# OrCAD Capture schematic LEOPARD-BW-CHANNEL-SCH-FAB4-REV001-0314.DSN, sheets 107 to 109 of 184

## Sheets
107 064_DDR4 DIMM CPU1 CHG-1: size A3; title: DDR4 DIMM CPU1 CHG-1
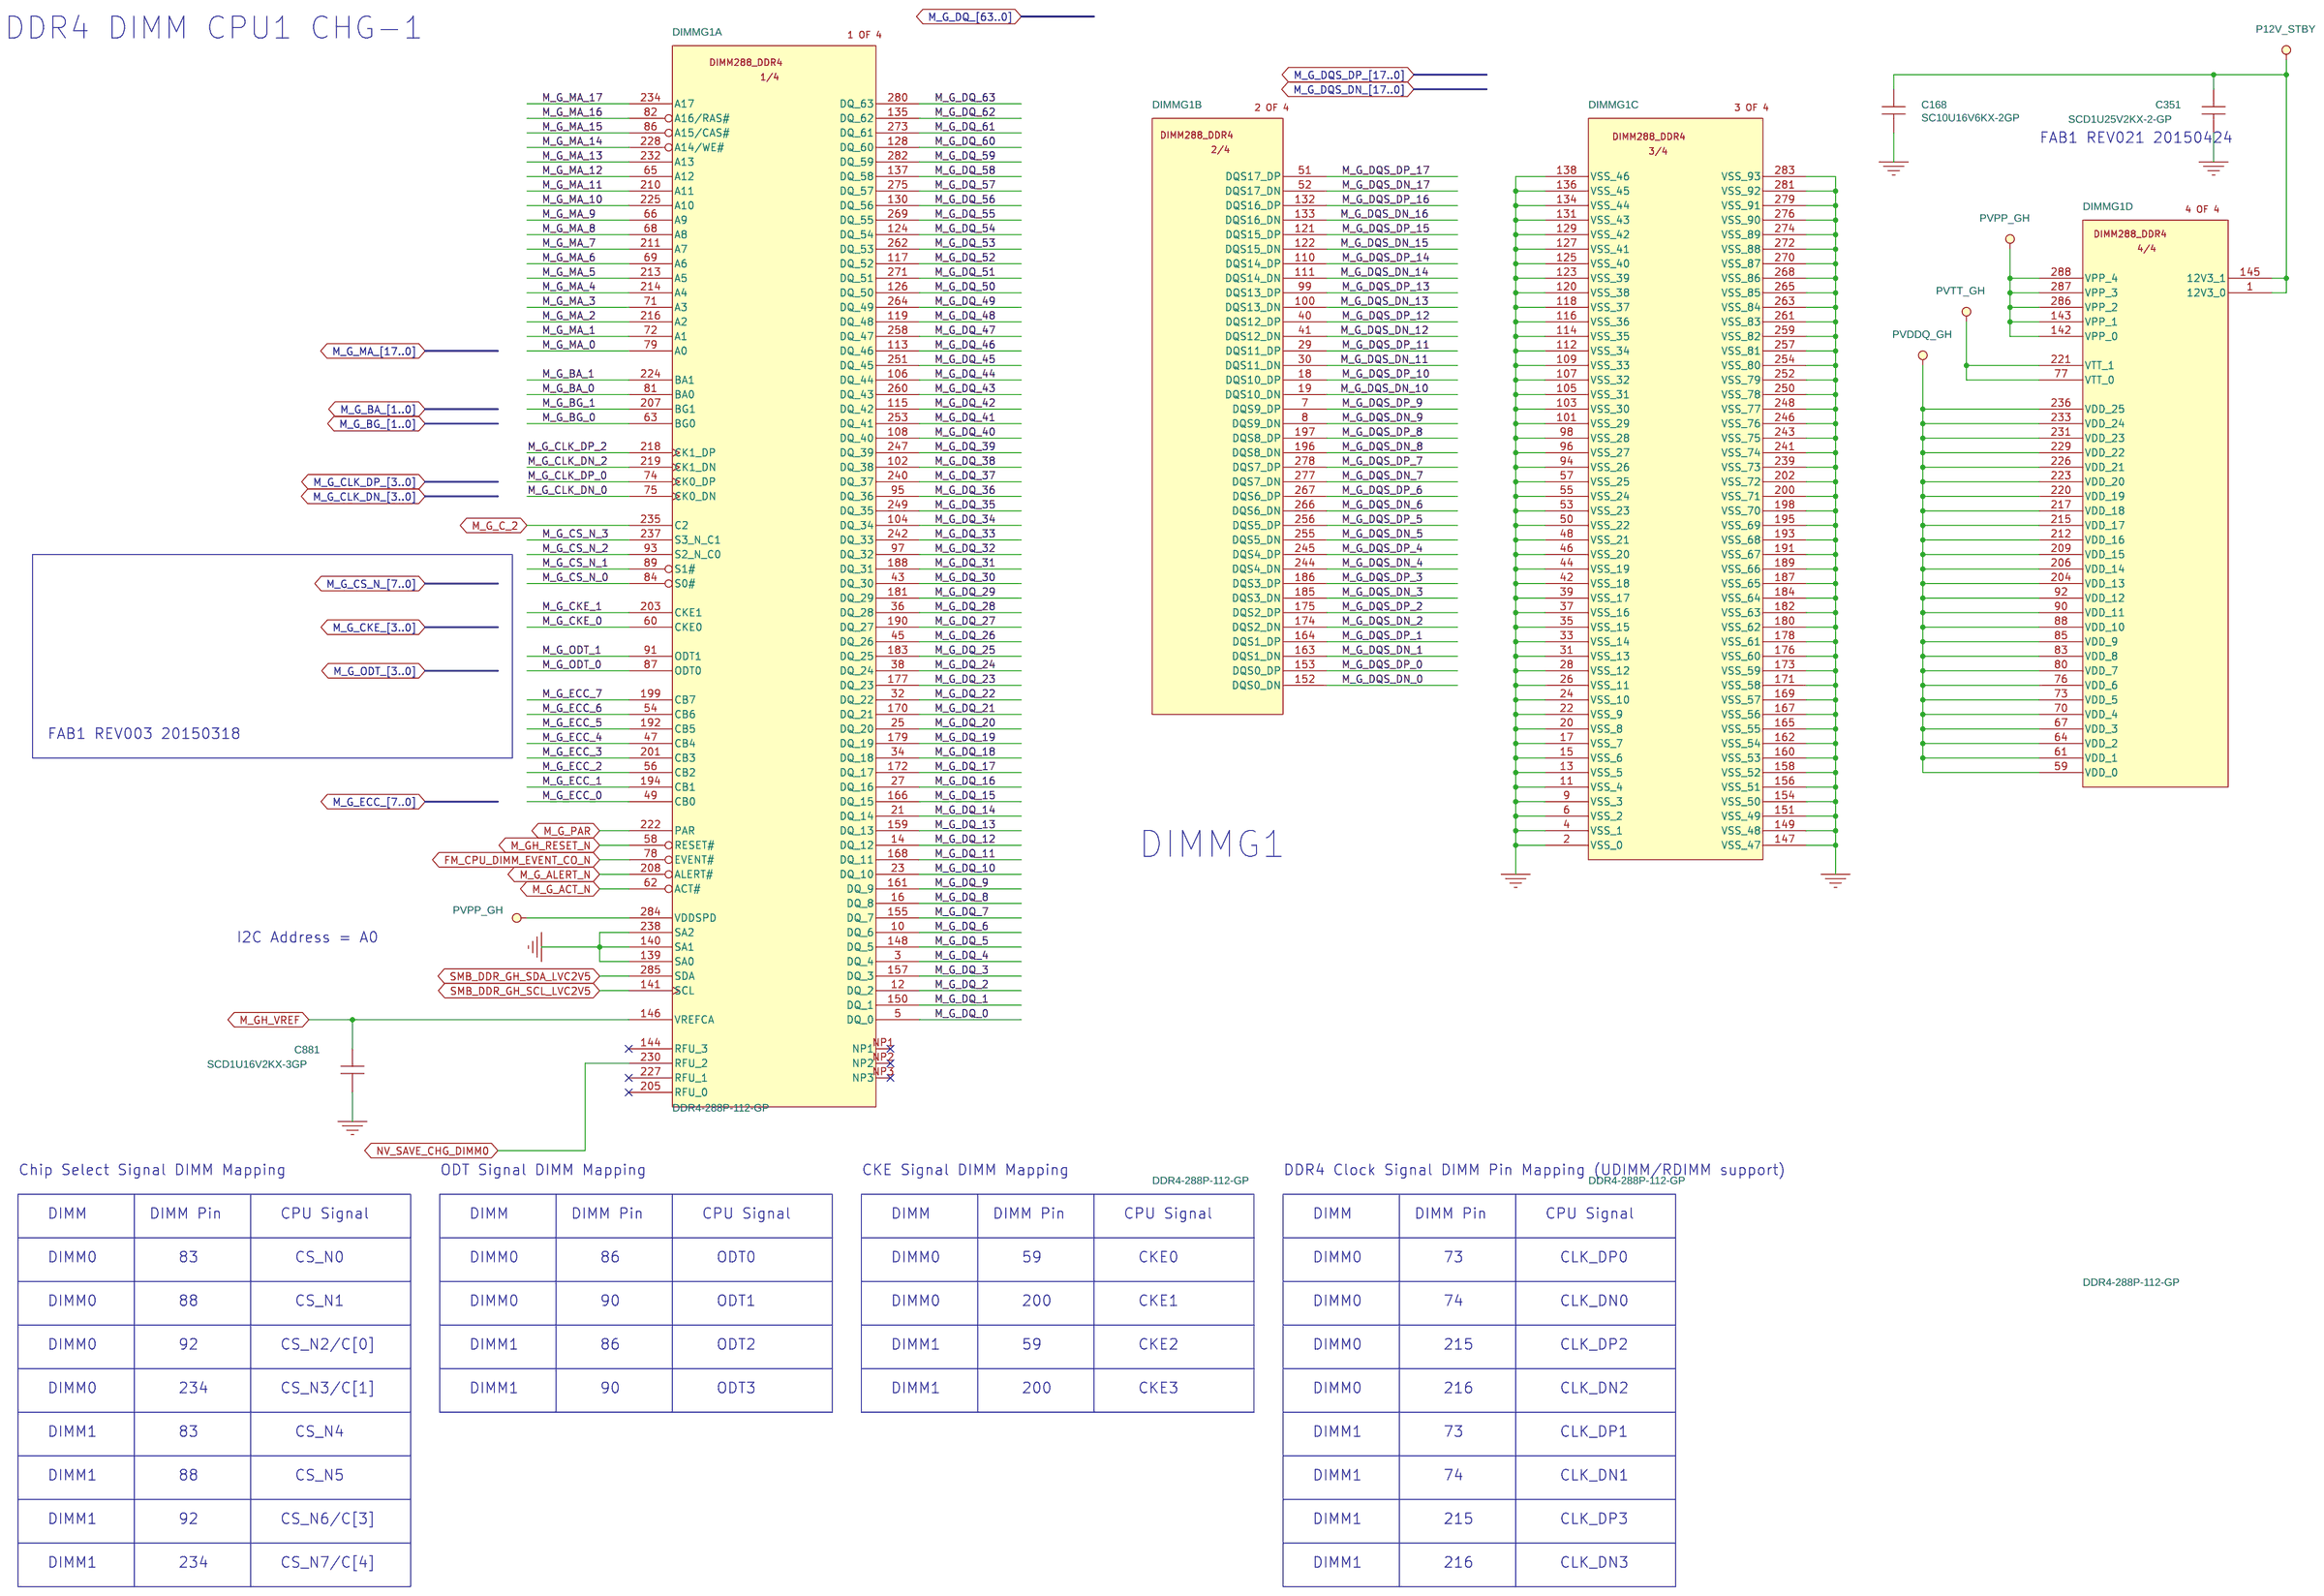
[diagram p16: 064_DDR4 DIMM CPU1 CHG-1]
108 063_DDR4 DIMM CPU1 CHF-2: size A3; title: DDR4 DIMM CPU1 CHF-2
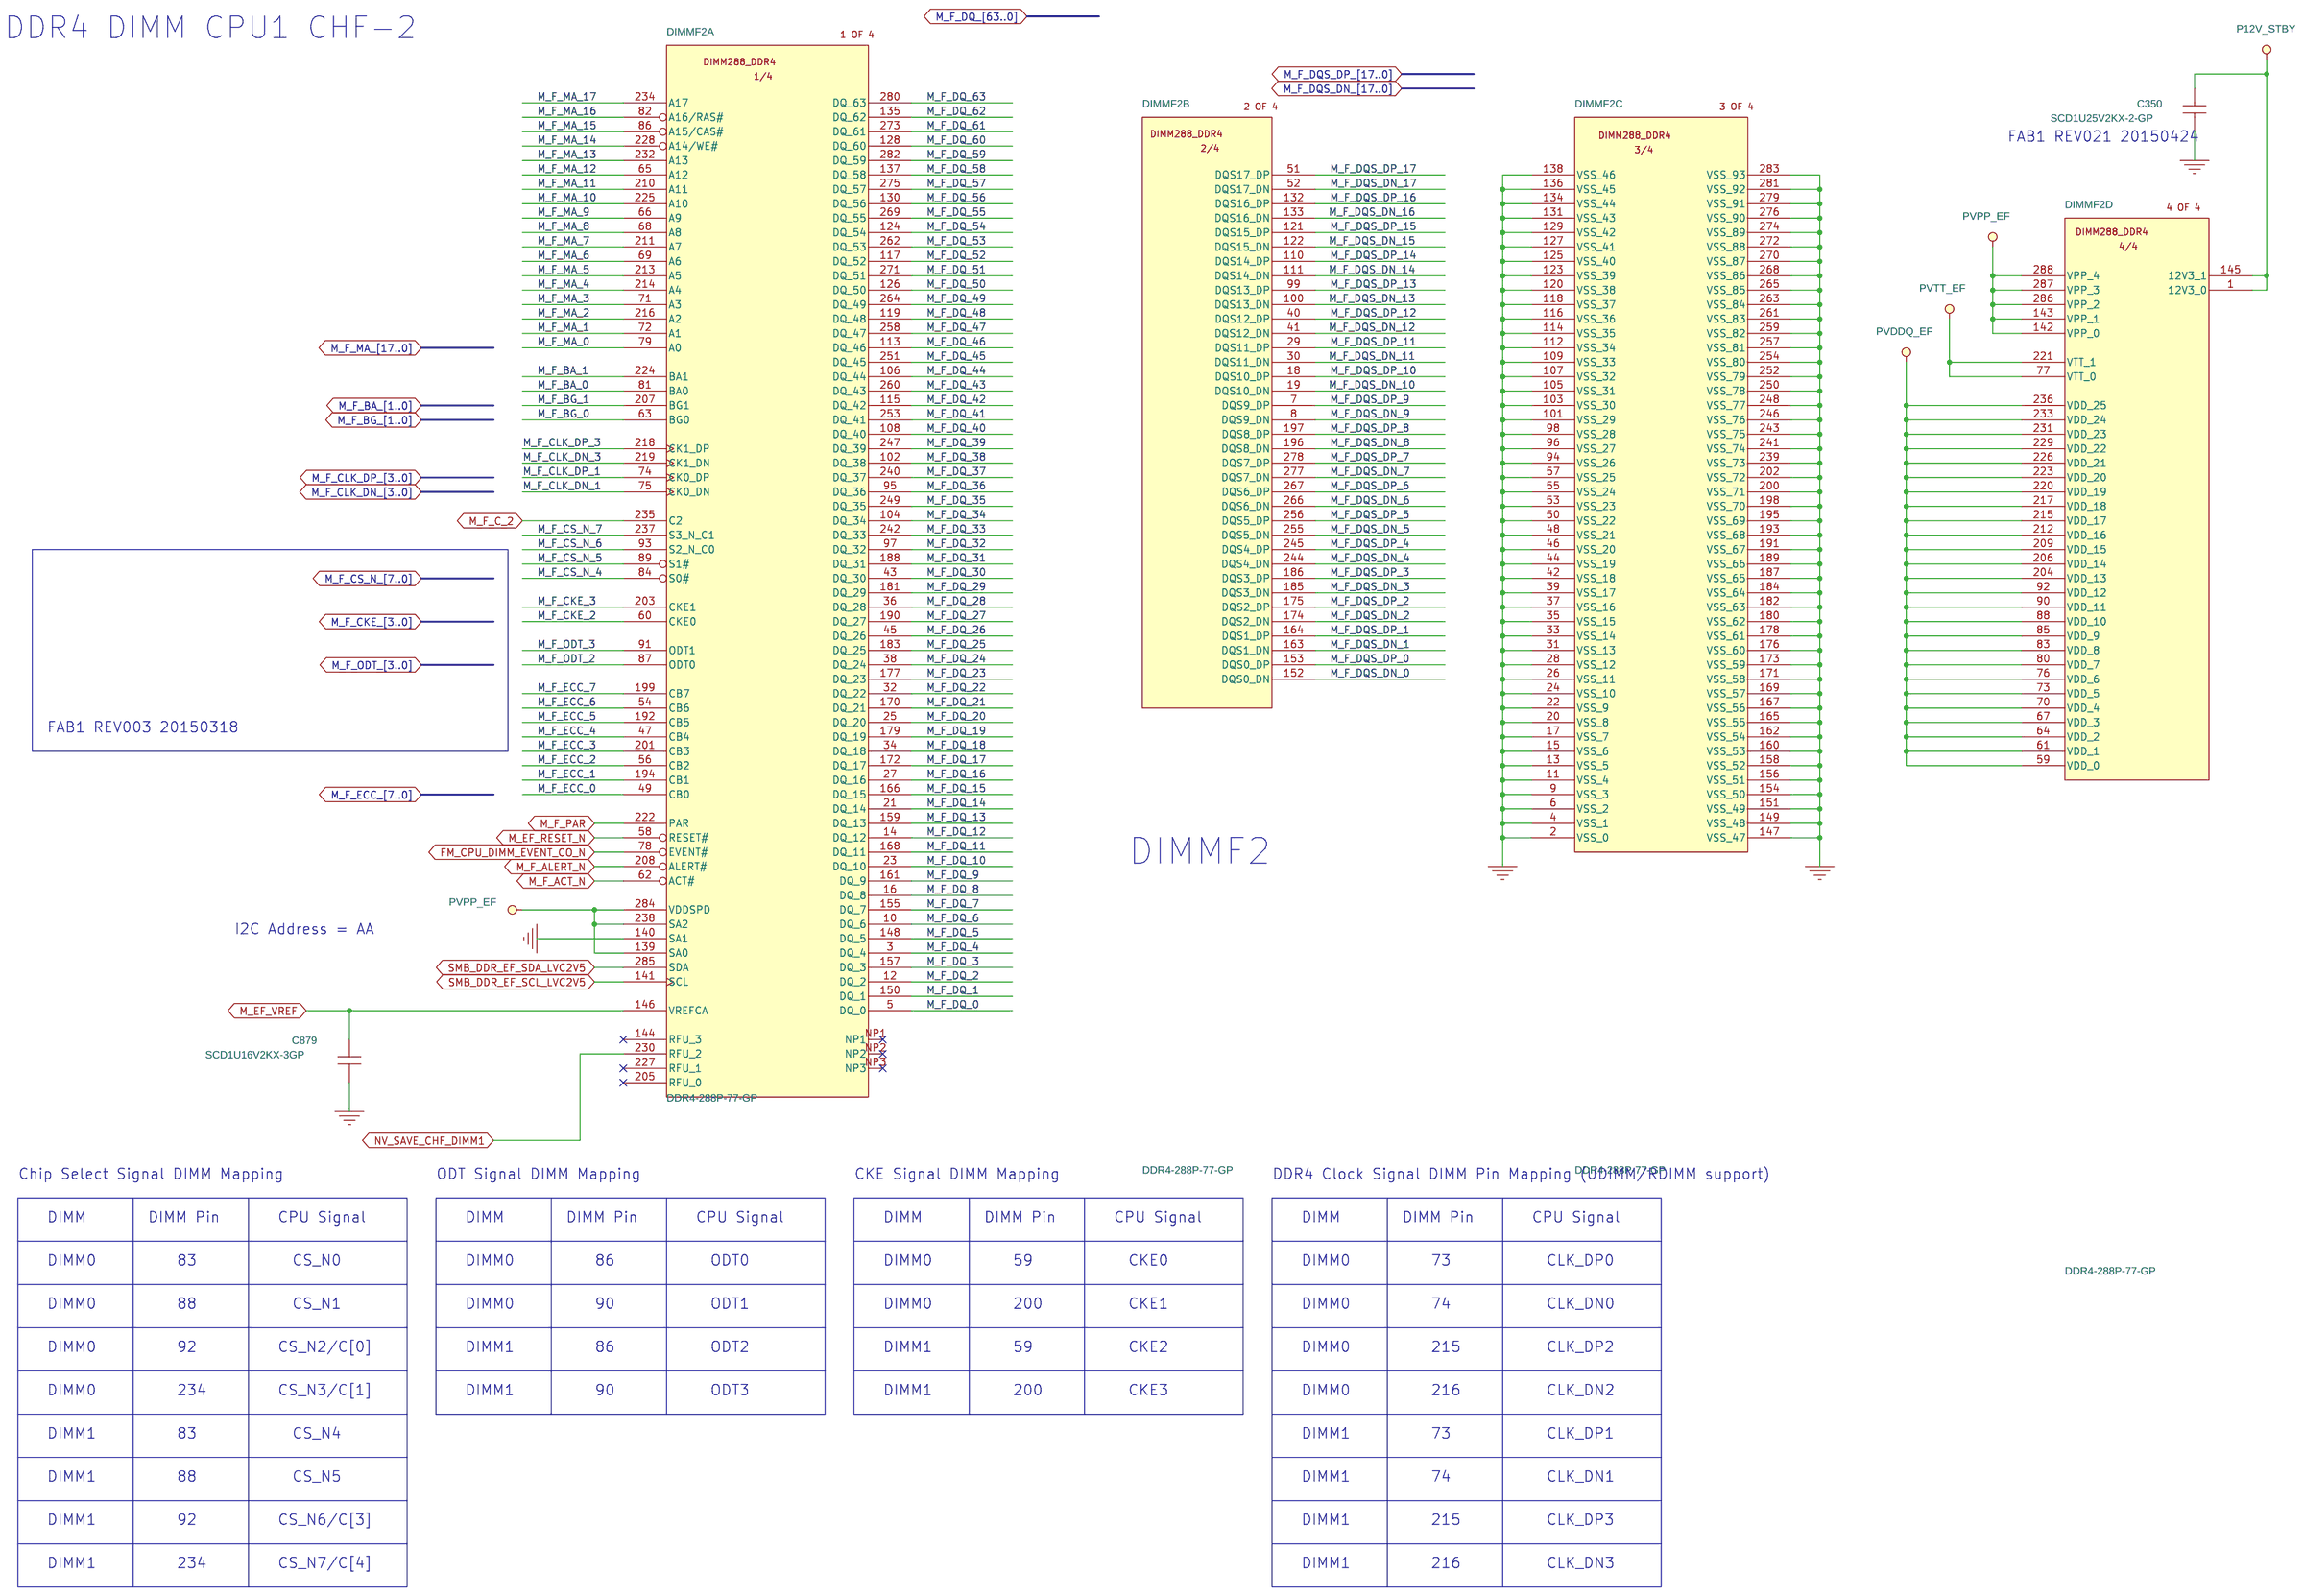
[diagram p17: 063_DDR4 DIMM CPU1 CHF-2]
109 062_DDR4 DIMM CPU1 CHF-1: size A3; title: DDR4 DIMM CPU1 CHF-1
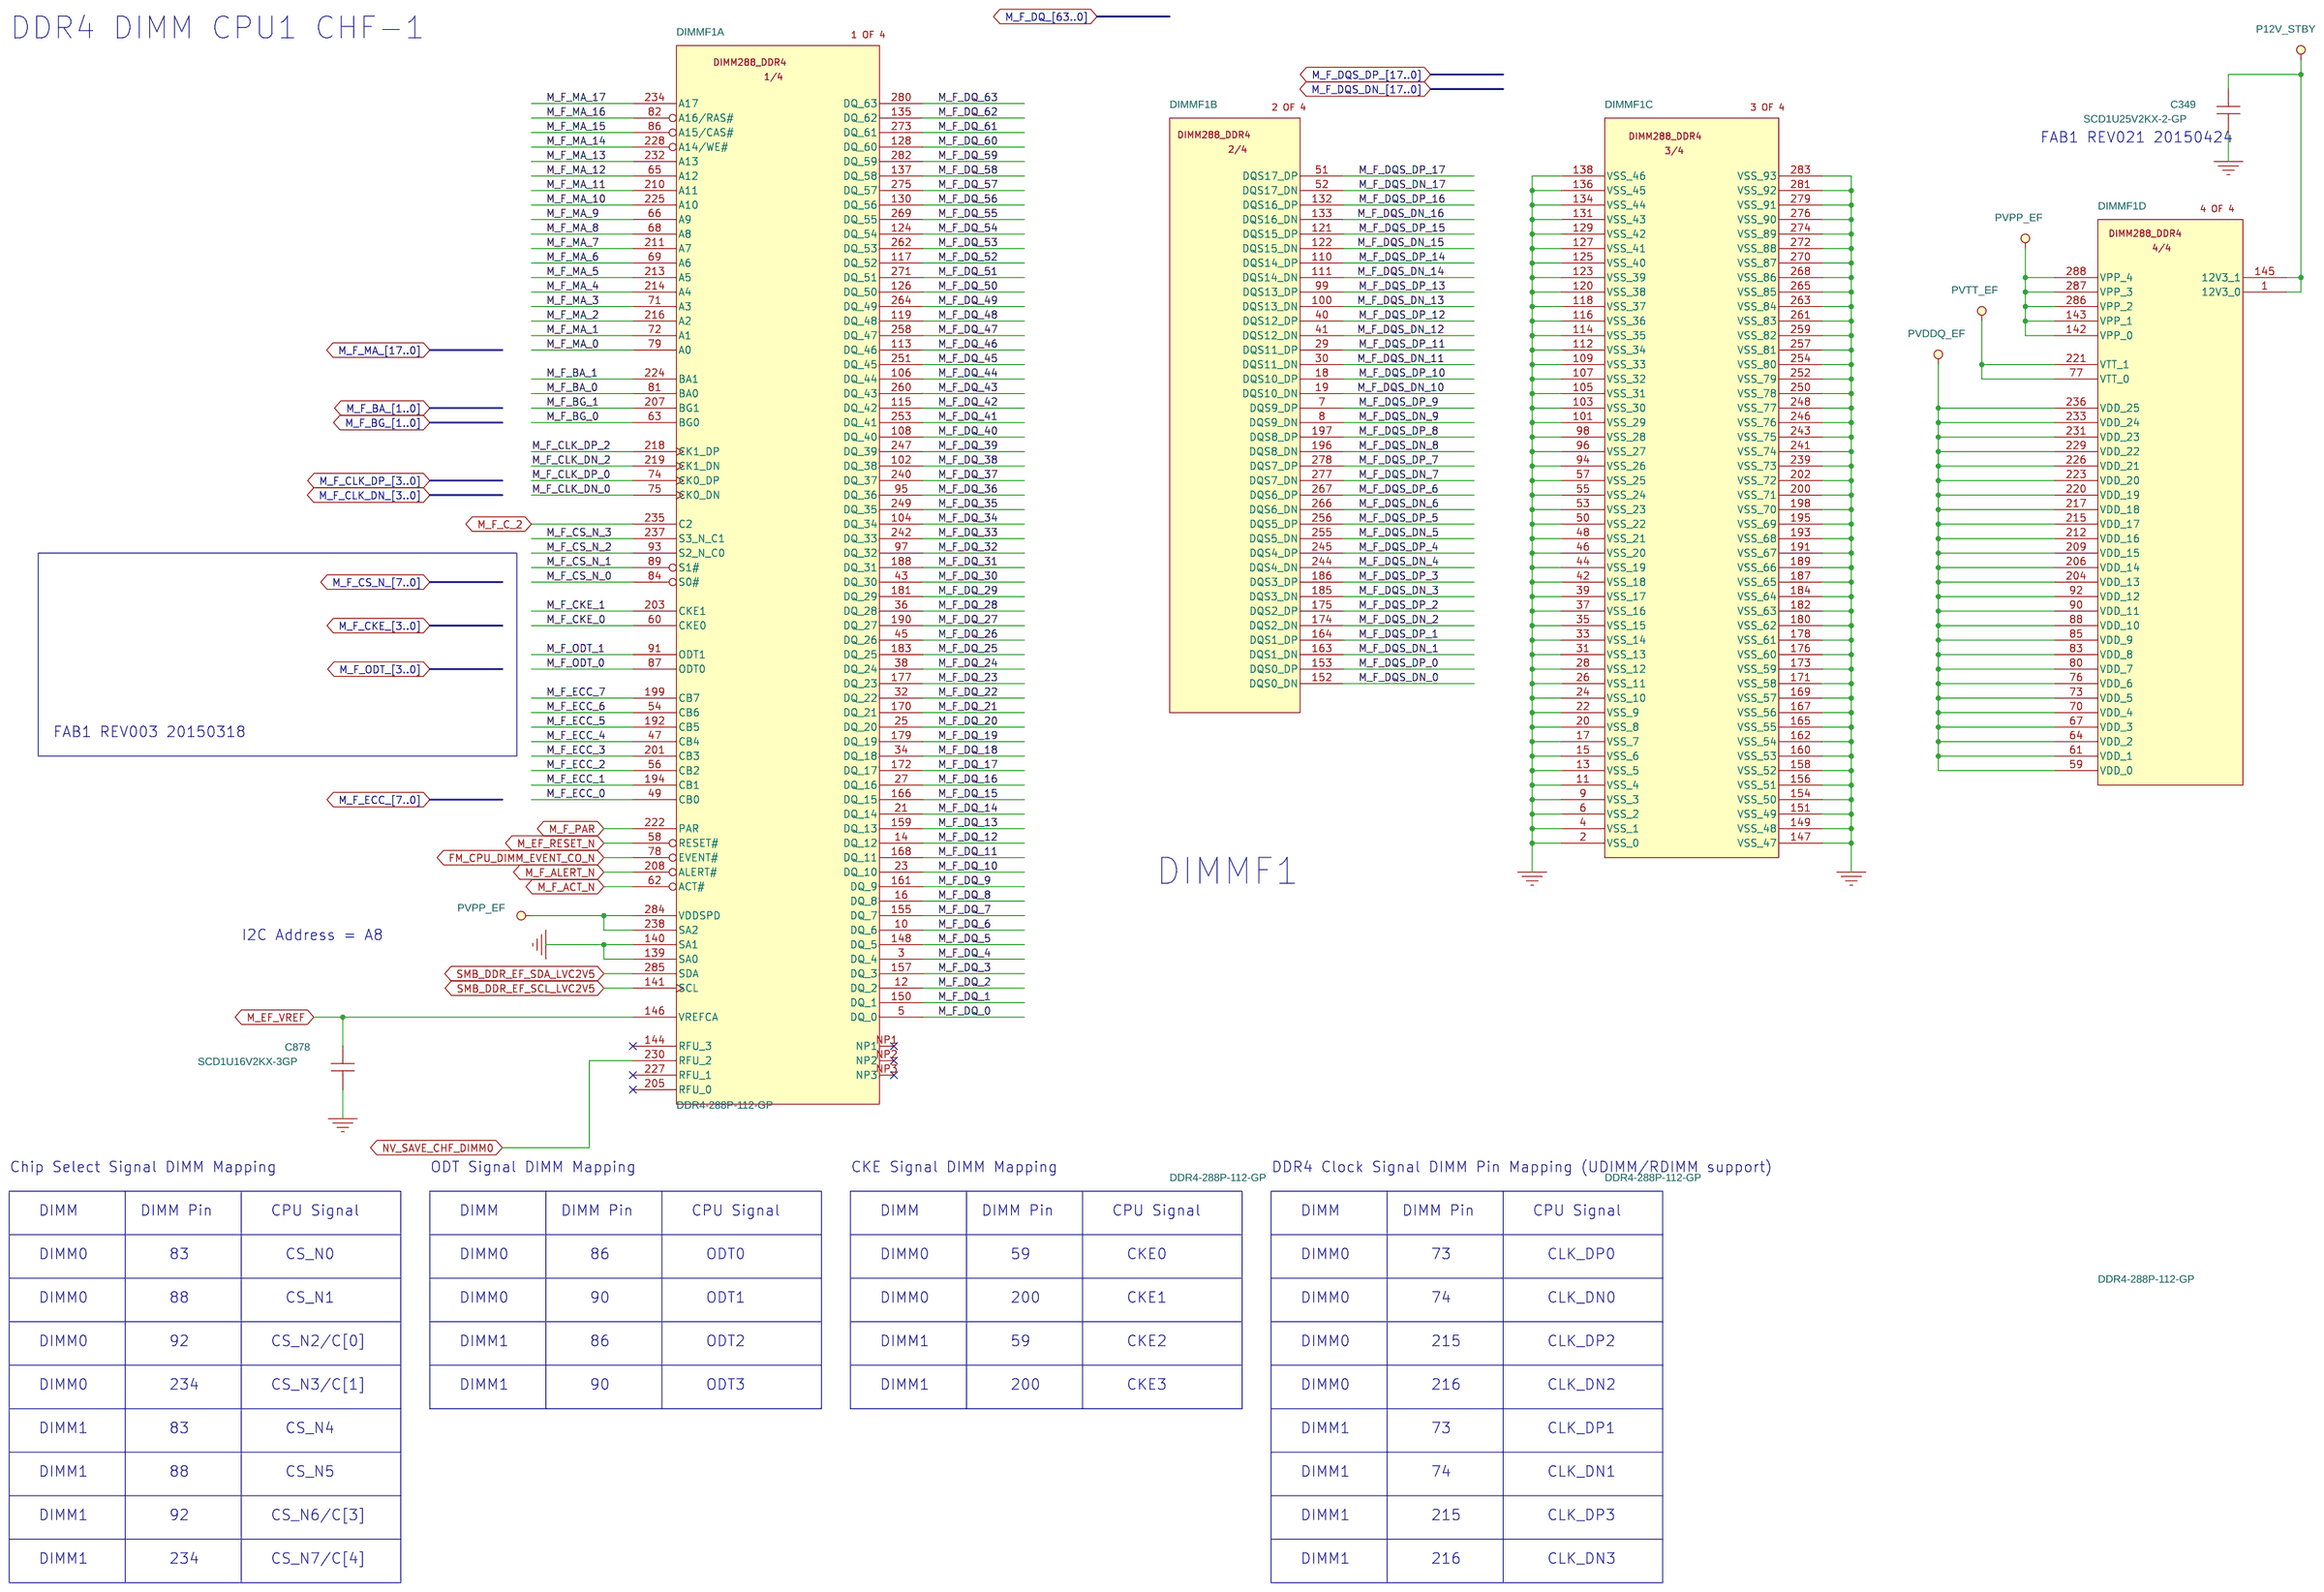
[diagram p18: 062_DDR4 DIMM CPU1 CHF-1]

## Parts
sheet 062_DDR4 DIMM CPU1 CHF-1
C349  SCD1U25V2KX-2-GP  [C402H22]
C878  SCD1U16V2KX-3GP  [C402H22]
DIMMF1  DDR4-288P-112-GP  [10124632-0001113LF]  (sections A,B,C,D)
sheet 063_DDR4 DIMM CPU1 CHF-2
C350  SCD1U25V2KX-2-GP  [C402H22]
C879  SCD1U16V2KX-3GP  [C402H22]
DIMMF2  DDR4-288P-77-GP  [10124632-0001113LF]  (sections A,B,C,D)
sheet 064_DDR4 DIMM CPU1 CHG-1
C168  SC10U16V6KX-2GP  [C1206H71]
C351  SCD1U25V2KX-2-GP  [C402H22]
C881  SCD1U16V2KX-3GP  [C402H22]
DIMMG1  DDR4-288P-112-GP  [10124632-0001113LF]  (sections A,B,C,D)

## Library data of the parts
C349-C351 = SCD1U25V2KX-2-GP: CHIP CAP C 0.1U 25V K0402 X7R; GREENDFACTOR: R2_SA;HF_SA;G_SA;; Part Number: 78.10422.2FL; Part Type: SMD-BCG4; SPEC: http://wpqssvr.wistron.com.tw:7001/wpqs/servlet/COM.qpart.Attachment?PartNumber=78.10422.2FL
C878 C879 C881 = SCD1U16V2KX-3GP: CHIP CAP C 0.1U 16V K0402 X7R; CATEGORIES: CAP_1.xV; GREENDFACTOR: R2_SA;HF_SA;G_SA;; MAIN_SOURCE: M; Part Number: 78.10421.2FL; Part Type: SMD-BCG; SPEC: http://wpqssvr.wistron.com.tw:7001/wpqs/servlet/COM.qpart.Attachment?PartNumber=78.10421.2FL
DIMMF1 DIMMG1 = DDR4-288P-112-GP: SKT DIMM DDR4 288P 10124632-0003001LF; GREENDFACTOR: R2_C;; POP?: 022.10010.0E11; Part Number: 022.10010.0B91; Part Type: SOCKET-G2; SPEC: http://wpqssvr.wistron.com.tw:7001/wpqs/servlet/COM.qpart.Attachment?PartNumber=022.10010.0B91
DIMMF2 = DDR4-288P-77-GP: SKT DIMM DDR4 288P 10124632-0001001LF; GREENDFACTOR: R2_SA;; POP?: 022.10010.0B11; Part Number: 22.10244.1A1; Part Type: SOCKET-G1; SPEC: http://wpqssvr.wistron.com.tw:7001/wpqs/servlet/COM.qpart.Attachment?PartNumber=22.10244.1A1
C168 = SC10U16V6KX-2GP: CHIP CAP C 10U 16V K1206 X7R; GREENDFACTOR: R2_SA;HF_SA;G_SA;; Part Number: 78.10621.22L; Part Type: SMD-BCG; SPEC: http://wpqssvr.wistron.com.tw:7001/wpqs/servlet/COM.qpart.Attachment?PartNumber=78.10621.22L

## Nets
GND: C168.2 C349.2 C350.2 C351.2 C878.2 C879.2 C881.2 DIMMF1.2(VSS_0) DIMMF1.4(VSS_1) DIMMF1.6(VSS_2) DIMMF1.9(VSS_3) DIMMF1.11(VSS_4) DIMMF1.13(VSS_5) DIMMF1.15(VSS_6) DIMMF1.17(VSS_7) DIMMF1.20(VSS_8) DIMMF1.22(VSS_9) DIMMF1.24(VSS_10) DIMMF1.26(VSS_11) DIMMF1.28(VSS_12) DIMMF1.31(VSS_13) DIMMF1.33(VSS_14) DIMMF1.35(VSS_15) DIMMF1.37(VSS_16) DIMMF1.39(VSS_17) DIMMF1.42(VSS_18) DIMMF1.44(VSS_19) DIMMF1.46(VSS_20) DIMMF1.48(VSS_21) DIMMF1.50(VSS_22) DIMMF1.53(VSS_23) DIMMF1.55(VSS_24) DIMMF1.57(VSS_25) DIMMF1.94(VSS_26) DIMMF1.96(VSS_27) DIMMF1.98(VSS_28) DIMMF1.101(VSS_29) DIMMF1.103(VSS_30) DIMMF1.105(VSS_31) DIMMF1.107(VSS_32) DIMMF1.109(VSS_33) DIMMF1.112(VSS_34) DIMMF1.114(VSS_35) DIMMF1.116(VSS_36) DIMMF1.118(VSS_37) DIMMF1.120(VSS_38) DIMMF1.123(VSS_39) DIMMF1.125(VSS_40) DIMMF1.127(VSS_41) DIMMF1.129(VSS_42) DIMMF1.131(VSS_43) DIMMF1.134(VSS_44) DIMMF1.136(VSS_45) DIMMF1.138(VSS_46) DIMMF1.139(SA0) DIMMF1.140(SA1) DIMMF1.147(VSS_47) DIMMF1.149(VSS_48) DIMMF1.151(VSS_49) DIMMF1.154(VSS_50) DIMMF1.156(VSS_51) DIMMF1.158(VSS_52) DIMMF1.160(VSS_53) DIMMF1.162(VSS_54) DIMMF1.165(VSS_55) DIMMF1.167(VSS_56) DIMMF1.169(VSS_57) DIMMF1.171(VSS_58) DIMMF1.173(VSS_59) DIMMF1.176(VSS_60) DIMMF1.178(VSS_61) DIMMF1.180(VSS_62) DIMMF1.182(VSS_63) DIMMF1.184(VSS_64) DIMMF1.187(VSS_65) DIMMF1.189(VSS_66) DIMMF1.191(VSS_67) DIMMF1.193(VSS_68) DIMMF1.195(VSS_69) DIMMF1.198(VSS_70) DIMMF1.200(VSS_71) DIMMF1.202(VSS_72) DIMMF1.239(VSS_73) DIMMF1.241(VSS_74) DIMMF1.243(VSS_75) DIMMF1.246(VSS_76) DIMMF1.248(VSS_77) DIMMF1.250(VSS_78) DIMMF1.252(VSS_79) DIMMF1.254(VSS_80) DIMMF1.257(VSS_81) DIMMF1.259(VSS_82) DIMMF1.261(VSS_83) DIMMF1.263(VSS_84) DIMMF1.265(VSS_85) DIMMF1.268(VSS_86) DIMMF1.270(VSS_87) DIMMF1.272(VSS_88) DIMMF1.274(VSS_89) DIMMF1.276(VSS_90) DIMMF1.279(VSS_91) DIMMF1.281(VSS_92) DIMMF1.283(VSS_93) DIMMF2.2(VSS_0) DIMMF2.4(VSS_1) DIMMF2.6(VSS_2) DIMMF2.9(VSS_3) DIMMF2.11(VSS_4) DIMMF2.13(VSS_5) DIMMF2.15(VSS_6) DIMMF2.17(VSS_7) DIMMF2.20(VSS_8) DIMMF2.22(VSS_9) DIMMF2.24(VSS_10) DIMMF2.26(VSS_11) DIMMF2.28(VSS_12) DIMMF2.31(VSS_13) DIMMF2.33(VSS_14) DIMMF2.35(VSS_15) DIMMF2.37(VSS_16) DIMMF2.39(VSS_17) DIMMF2.42(VSS_18) DIMMF2.44(VSS_19) DIMMF2.46(VSS_20) DIMMF2.48(VSS_21) DIMMF2.50(VSS_22) DIMMF2.53(VSS_23) DIMMF2.55(VSS_24) DIMMF2.57(VSS_25) DIMMF2.94(VSS_26) DIMMF2.96(VSS_27) DIMMF2.98(VSS_28) DIMMF2.101(VSS_29) DIMMF2.103(VSS_30) DIMMF2.105(VSS_31) DIMMF2.107(VSS_32) DIMMF2.109(VSS_33) DIMMF2.112(VSS_34) DIMMF2.114(VSS_35) DIMMF2.116(VSS_36) DIMMF2.118(VSS_37) DIMMF2.120(VSS_38) DIMMF2.123(VSS_39) DIMMF2.125(VSS_40) DIMMF2.127(VSS_41) DIMMF2.129(VSS_42) DIMMF2.131(VSS_43) DIMMF2.134(VSS_44) DIMMF2.136(VSS_45) DIMMF2.138(VSS_46) DIMMF2.140(SA1) DIMMF2.147(VSS_47) DIMMF2.149(VSS_48) DIMMF2.151(VSS_49) DIMMF2.154(VSS_50) DIMMF2.156(VSS_51) DIMMF2.158(VSS_52) DIMMF2.160(VSS_53) DIMMF2.162(VSS_54) DIMMF2.165(VSS_55) DIMMF2.167(VSS_56) DIMMF2.169(VSS_57) DIMMF2.171(VSS_58) DIMMF2.173(VSS_59) DIMMF2.176(VSS_60) DIMMF2.178(VSS_61) DIMMF2.180(VSS_62) DIMMF2.182(VSS_63) DIMMF2.184(VSS_64) DIMMF2.187(VSS_65) DIMMF2.189(VSS_66) DIMMF2.191(VSS_67) DIMMF2.193(VSS_68) DIMMF2.195(VSS_69) DIMMF2.198(VSS_70) DIMMF2.200(VSS_71) DIMMF2.202(VSS_72) DIMMF2.239(VSS_73) DIMMF2.241(VSS_74) DIMMF2.243(VSS_75) DIMMF2.246(VSS_76) DIMMF2.248(VSS_77) DIMMF2.250(VSS_78) DIMMF2.252(VSS_79) DIMMF2.254(VSS_80) DIMMF2.257(VSS_81) DIMMF2.259(VSS_82) DIMMF2.261(VSS_83) DIMMF2.263(VSS_84) DIMMF2.265(VSS_85) DIMMF2.268(VSS_86) DIMMF2.270(VSS_87) DIMMF2.272(VSS_88) DIMMF2.274(VSS_89) DIMMF2.276(VSS_90) DIMMF2.279(VSS_91) DIMMF2.281(VSS_92) DIMMF2.283(VSS_93) DIMMG1.2(VSS_0) DIMMG1.4(VSS_1) DIMMG1.6(VSS_2) DIMMG1.9(VSS_3) DIMMG1.11(VSS_4) DIMMG1.13(VSS_5) DIMMG1.15(VSS_6) DIMMG1.17(VSS_7) DIMMG1.20(VSS_8) DIMMG1.22(VSS_9) DIMMG1.24(VSS_10) DIMMG1.26(VSS_11) DIMMG1.28(VSS_12) DIMMG1.31(VSS_13) DIMMG1.33(VSS_14) DIMMG1.35(VSS_15) DIMMG1.37(VSS_16) DIMMG1.39(VSS_17) DIMMG1.42(VSS_18) DIMMG1.44(VSS_19) DIMMG1.46(VSS_20) DIMMG1.48(VSS_21) DIMMG1.50(VSS_22) DIMMG1.53(VSS_23) DIMMG1.55(VSS_24) DIMMG1.57(VSS_25) DIMMG1.94(VSS_26) DIMMG1.96(VSS_27) DIMMG1.98(VSS_28) DIMMG1.101(VSS_29) DIMMG1.103(VSS_30) DIMMG1.105(VSS_31) DIMMG1.107(VSS_32) DIMMG1.109(VSS_33) DIMMG1.112(VSS_34) DIMMG1.114(VSS_35) DIMMG1.116(VSS_36) DIMMG1.118(VSS_37) DIMMG1.120(VSS_38) DIMMG1.123(VSS_39) DIMMG1.125(VSS_40) DIMMG1.127(VSS_41) DIMMG1.129(VSS_42) DIMMG1.131(VSS_43) DIMMG1.134(VSS_44) DIMMG1.136(VSS_45) DIMMG1.138(VSS_46) DIMMG1.139(SA0) DIMMG1.140(SA1) DIMMG1.147(VSS_47) DIMMG1.149(VSS_48) DIMMG1.151(VSS_49) DIMMG1.154(VSS_50) DIMMG1.156(VSS_51) DIMMG1.158(VSS_52) DIMMG1.160(VSS_53) DIMMG1.162(VSS_54) DIMMG1.165(VSS_55) DIMMG1.167(VSS_56) DIMMG1.169(VSS_57) DIMMG1.171(VSS_58) DIMMG1.173(VSS_59) DIMMG1.176(VSS_60) DIMMG1.178(VSS_61) DIMMG1.180(VSS_62) DIMMG1.182(VSS_63) DIMMG1.184(VSS_64) DIMMG1.187(VSS_65) DIMMG1.189(VSS_66) DIMMG1.191(VSS_67) DIMMG1.193(VSS_68) DIMMG1.195(VSS_69) DIMMG1.198(VSS_70) DIMMG1.200(VSS_71) DIMMG1.202(VSS_72) DIMMG1.238(SA2) DIMMG1.239(VSS_73) DIMMG1.241(VSS_74) DIMMG1.243(VSS_75) DIMMG1.246(VSS_76) DIMMG1.248(VSS_77) DIMMG1.250(VSS_78) DIMMG1.252(VSS_79) DIMMG1.254(VSS_80) DIMMG1.257(VSS_81) DIMMG1.259(VSS_82) DIMMG1.261(VSS_83) DIMMG1.263(VSS_84) DIMMG1.265(VSS_85) DIMMG1.268(VSS_86) DIMMG1.270(VSS_87) DIMMG1.272(VSS_88) DIMMG1.274(VSS_89) DIMMG1.276(VSS_90) DIMMG1.279(VSS_91) DIMMG1.281(VSS_92) DIMMG1.283(VSS_93) ; also on sheet 1 2 3 4 5 6 7 8 9 10 11 12 13 14 15 16 17 18 19 20 21 22 23 24 25 26 27 28 29 30 31 32 33 34 35 36 37 38 39 44 46 47 49 50 51 52 53 54 55 56 57 58 59 60 61 62 63 64 65 66 69 70 71 73 74 75 76 78 79 80 81 82 83 84 86 87 88 89 90 91 92 93 94 95 96 97 98 99 100 101 102 103 104 105 106 110 111 112 113 114 115 116 117 118 119 128 129 138 139 159 160 161 166 168 169 170 171 172 173 174 175 176 177 180 181 182 183 184
P12V_STBY: C168.1 C349.1 C350.1 C351.1 DIMMF1.1(12V3_0) DIMMF1.145(12V3_1) DIMMF2.1(12V3_0) DIMMF2.145(12V3_1) DIMMG1.1(12V3_0) DIMMG1.145(12V3_1) ; also on sheet 2 3 4 7 9 10 11 12 13 17 18 22 23 27 28 32 36 59 60 75 95 104 105 106 110 111 112 113 114 115 116 117 118 119
PVDDQ_EF: DIMMF1.59(VDD_0) DIMMF1.61(VDD_1) DIMMF1.64(VDD_2) DIMMF1.67(VDD_3) DIMMF1.70(VDD_4) DIMMF1.73(VDD_5) DIMMF1.76(VDD_6) DIMMF1.80(VDD_7) DIMMF1.83(VDD_8) DIMMF1.85(VDD_9) DIMMF1.88(VDD_10) DIMMF1.90(VDD_11) DIMMF1.92(VDD_12) DIMMF1.204(VDD_13) DIMMF1.206(VDD_14) DIMMF1.209(VDD_15) DIMMF1.212(VDD_16) DIMMF1.215(VDD_17) DIMMF1.217(VDD_18) DIMMF1.220(VDD_19) DIMMF1.223(VDD_20) DIMMF1.226(VDD_21) DIMMF1.229(VDD_22) DIMMF1.231(VDD_23) DIMMF1.233(VDD_24) DIMMF1.236(VDD_25) DIMMF2.59(VDD_0) DIMMF2.61(VDD_1) DIMMF2.64(VDD_2) DIMMF2.67(VDD_3) DIMMF2.70(VDD_4) DIMMF2.73(VDD_5) DIMMF2.76(VDD_6) DIMMF2.80(VDD_7) DIMMF2.83(VDD_8) DIMMF2.85(VDD_9) DIMMF2.88(VDD_10) DIMMF2.90(VDD_11) DIMMF2.92(VDD_12) DIMMF2.204(VDD_13) DIMMF2.206(VDD_14) DIMMF2.209(VDD_15) DIMMF2.212(VDD_16) DIMMF2.215(VDD_17) DIMMF2.217(VDD_18) DIMMF2.220(VDD_19) DIMMF2.223(VDD_20) DIMMF2.226(VDD_21) DIMMF2.229(VDD_22) DIMMF2.231(VDD_23) DIMMF2.233(VDD_24) DIMMF2.236(VDD_25) ; also on sheet 18 20 45 97 110 111 120 129
PVDDQ_GH: DIMMG1.59(VDD_0) DIMMG1.61(VDD_1) DIMMG1.64(VDD_2) DIMMG1.67(VDD_3) DIMMG1.70(VDD_4) DIMMG1.73(VDD_5) DIMMG1.76(VDD_6) DIMMG1.80(VDD_7) DIMMG1.83(VDD_8) DIMMG1.85(VDD_9) DIMMG1.88(VDD_10) DIMMG1.90(VDD_11) DIMMG1.92(VDD_12) DIMMG1.204(VDD_13) DIMMG1.206(VDD_14) DIMMG1.209(VDD_15) DIMMG1.212(VDD_16) DIMMG1.215(VDD_17) DIMMG1.217(VDD_18) DIMMG1.220(VDD_19) DIMMG1.223(VDD_20) DIMMG1.226(VDD_21) DIMMG1.229(VDD_22) DIMMG1.231(VDD_23) DIMMG1.233(VDD_24) DIMMG1.236(VDD_25) ; also on sheet 13 15 45 97 104 105 106 120 129
FM_CPU_DIMM_EVENT_CO_N: DIMMF1.78(EVENT#) DIMMF2.78(EVENT#) DIMMG1.78(EVENT#) ; also on sheet 98 104 105 106 110 111 112 113 114 115 116 117 118 119
M_EF_RESET_N: DIMMF1.58(RESET#) DIMMF2.58(RESET#) ; also on sheet 110 111 129
M_EF_VREF: C878.1 C879.1 DIMMF1.146(VREFCA) DIMMF2.146(VREFCA) ; also on sheet 110 111 129
M_F_ACT_N: DIMMF1.62(ACT#) DIMMF2.62(ACT#) ; also on sheet 126
M_F_ALERT_N: DIMMF1.208(ALERT#) DIMMF2.208(ALERT#) ; also on sheet 126
M_F_BA_0: DIMMF1.81(BA0) DIMMF2.81(BA0) ; also on sheet 126
M_F_BA_1: DIMMF1.224(BA1) DIMMF2.224(BA1) ; also on sheet 126
M_F_BG_0: DIMMF1.63(BG0) DIMMF2.63(BG0) ; also on sheet 126
M_F_BG_1: DIMMF1.207(BG1) DIMMF2.207(BG1) ; also on sheet 126
M_F_C_2: DIMMF1.235(C2) DIMMF2.235(C2) ; also on sheet 126
M_F_CKE_0: DIMMF1.60(CKE0) ; also on sheet 126
M_F_CKE_1: DIMMF1.203(CKE1) ; also on sheet 126
M_F_CKE_2: DIMMF2.60(CKE0) ; also on sheet 126
M_F_CKE_3: DIMMF2.203(CKE1) ; also on sheet 126
M_F_CLK_DN_0: DIMMF1.75(CK0_DN) ; also on sheet 126
M_F_CLK_DN_1: DIMMF2.75(CK0_DN) ; also on sheet 126
M_F_CLK_DN_2: DIMMF1.219(CK1_DN) ; also on sheet 126
M_F_CLK_DN_3: DIMMF2.219(CK1_DN) ; also on sheet 126
M_F_CLK_DP_0: DIMMF1.74(CK0_DP) ; also on sheet 126
M_F_CLK_DP_1: DIMMF2.74(CK0_DP) ; also on sheet 126
M_F_CLK_DP_2: DIMMF1.218(CK1_DP) ; also on sheet 126
M_F_CLK_DP_3: DIMMF2.218(CK1_DP) ; also on sheet 126
M_F_CS_N_0: DIMMF1.84(S0#) ; also on sheet 126
M_F_CS_N_1: DIMMF1.89(S1#) ; also on sheet 126
M_F_CS_N_2: DIMMF1.93(S2_N_C0) ; also on sheet 126
M_F_CS_N_3: DIMMF1.237(S3_N_C1) ; also on sheet 126
M_F_CS_N_4: DIMMF2.84(S0#) ; also on sheet 126
M_F_CS_N_5: DIMMF2.89(S1#) ; also on sheet 126
M_F_CS_N_6: DIMMF2.93(S2_N_C0) ; also on sheet 126
M_F_CS_N_7: DIMMF2.237(S3_N_C1) ; also on sheet 126
M_F_DQ_0: DIMMF1.5(DQ_0) DIMMF2.5(DQ_0) ; also on sheet 126
M_F_DQ_1: DIMMF1.150(DQ_1) DIMMF2.150(DQ_1) ; also on sheet 126
M_F_DQ_2: DIMMF1.12(DQ_2) DIMMF2.12(DQ_2) ; also on sheet 126
M_F_DQ_3: DIMMF1.157(DQ_3) DIMMF2.157(DQ_3) ; also on sheet 126
M_F_DQ_4: DIMMF1.3(DQ_4) DIMMF2.3(DQ_4) ; also on sheet 126
M_F_DQ_5: DIMMF1.148(DQ_5) DIMMF2.148(DQ_5) ; also on sheet 126
M_F_DQ_6: DIMMF1.10(DQ_6) DIMMF2.10(DQ_6) ; also on sheet 126
M_F_DQ_7: DIMMF1.155(DQ_7) DIMMF2.155(DQ_7) ; also on sheet 126
M_F_DQ_8: DIMMF1.16(DQ_8) DIMMF2.16(DQ_8) ; also on sheet 126
M_F_DQ_9: DIMMF1.161(DQ_9) DIMMF2.161(DQ_9) ; also on sheet 126
M_F_DQ_10: DIMMF1.23(DQ_10) DIMMF2.23(DQ_10) ; also on sheet 126
M_F_DQ_11: DIMMF1.168(DQ_11) DIMMF2.168(DQ_11) ; also on sheet 126
M_F_DQ_12: DIMMF1.14(DQ_12) DIMMF2.14(DQ_12) ; also on sheet 126
M_F_DQ_13: DIMMF1.159(DQ_13) DIMMF2.159(DQ_13) ; also on sheet 126
M_F_DQ_14: DIMMF1.21(DQ_14) DIMMF2.21(DQ_14) ; also on sheet 126
M_F_DQ_15: DIMMF1.166(DQ_15) DIMMF2.166(DQ_15) ; also on sheet 126
M_F_DQ_16: DIMMF1.27(DQ_16) DIMMF2.27(DQ_16) ; also on sheet 126
M_F_DQ_17: DIMMF1.172(DQ_17) DIMMF2.172(DQ_17) ; also on sheet 126
M_F_DQ_18: DIMMF1.34(DQ_18) DIMMF2.34(DQ_18) ; also on sheet 126
M_F_DQ_19: DIMMF1.179(DQ_19) DIMMF2.179(DQ_19) ; also on sheet 126
M_F_DQ_20: DIMMF1.25(DQ_20) DIMMF2.25(DQ_20) ; also on sheet 126
M_F_DQ_21: DIMMF1.170(DQ_21) DIMMF2.170(DQ_21) ; also on sheet 126
M_F_DQ_22: DIMMF1.32(DQ_22) DIMMF2.32(DQ_22) ; also on sheet 126
M_F_DQ_23: DIMMF1.177(DQ_23) DIMMF2.177(DQ_23) ; also on sheet 126
M_F_DQ_24: DIMMF1.38(DQ_24) DIMMF2.38(DQ_24) ; also on sheet 126
M_F_DQ_25: DIMMF1.183(DQ_25) DIMMF2.183(DQ_25) ; also on sheet 126
M_F_DQ_26: DIMMF1.45(DQ_26) DIMMF2.45(DQ_26) ; also on sheet 126
M_F_DQ_27: DIMMF1.190(DQ_27) DIMMF2.190(DQ_27) ; also on sheet 126
M_F_DQ_28: DIMMF1.36(DQ_28) DIMMF2.36(DQ_28) ; also on sheet 126
M_F_DQ_29: DIMMF1.181(DQ_29) DIMMF2.181(DQ_29) ; also on sheet 126
M_F_DQ_30: DIMMF1.43(DQ_30) DIMMF2.43(DQ_30) ; also on sheet 126
M_F_DQ_31: DIMMF1.188(DQ_31) DIMMF2.188(DQ_31) ; also on sheet 126
M_F_DQ_32: DIMMF1.97(DQ_32) DIMMF2.97(DQ_32) ; also on sheet 126
M_F_DQ_33: DIMMF1.242(DQ_33) DIMMF2.242(DQ_33) ; also on sheet 126
M_F_DQ_34: DIMMF1.104(DQ_34) DIMMF2.104(DQ_34) ; also on sheet 126
M_F_DQ_35: DIMMF1.249(DQ_35) DIMMF2.249(DQ_35) ; also on sheet 126
M_F_DQ_36: DIMMF1.95(DQ_36) DIMMF2.95(DQ_36) ; also on sheet 126
M_F_DQ_37: DIMMF1.240(DQ_37) DIMMF2.240(DQ_37) ; also on sheet 126
M_F_DQ_38: DIMMF1.102(DQ_38) DIMMF2.102(DQ_38) ; also on sheet 126
M_F_DQ_39: DIMMF1.247(DQ_39) DIMMF2.247(DQ_39) ; also on sheet 126
M_F_DQ_40: DIMMF1.108(DQ_40) DIMMF2.108(DQ_40) ; also on sheet 126
M_F_DQ_41: DIMMF1.253(DQ_41) DIMMF2.253(DQ_41) ; also on sheet 126
M_F_DQ_42: DIMMF1.115(DQ_42) DIMMF2.115(DQ_42) ; also on sheet 126
M_F_DQ_43: DIMMF1.260(DQ_43) DIMMF2.260(DQ_43) ; also on sheet 126
M_F_DQ_44: DIMMF1.106(DQ_44) DIMMF2.106(DQ_44) ; also on sheet 126
M_F_DQ_45: DIMMF1.251(DQ_45) DIMMF2.251(DQ_45) ; also on sheet 126
M_F_DQ_46: DIMMF1.113(DQ_46) DIMMF2.113(DQ_46) ; also on sheet 126
M_F_DQ_47: DIMMF1.258(DQ_47) DIMMF2.258(DQ_47) ; also on sheet 126
M_F_DQ_48: DIMMF1.119(DQ_48) DIMMF2.119(DQ_48) ; also on sheet 126
M_F_DQ_49: DIMMF1.264(DQ_49) DIMMF2.264(DQ_49) ; also on sheet 126
M_F_DQ_50: DIMMF1.126(DQ_50) DIMMF2.126(DQ_50) ; also on sheet 126
M_F_DQ_51: DIMMF1.271(DQ_51) DIMMF2.271(DQ_51) ; also on sheet 126
M_F_DQ_52: DIMMF1.117(DQ_52) DIMMF2.117(DQ_52) ; also on sheet 126
M_F_DQ_53: DIMMF1.262(DQ_53) DIMMF2.262(DQ_53) ; also on sheet 126
M_F_DQ_54: DIMMF1.124(DQ_54) DIMMF2.124(DQ_54) ; also on sheet 126
M_F_DQ_55: DIMMF1.269(DQ_55) DIMMF2.269(DQ_55) ; also on sheet 126
M_F_DQ_56: DIMMF1.130(DQ_56) DIMMF2.130(DQ_56) ; also on sheet 126
M_F_DQ_57: DIMMF1.275(DQ_57) DIMMF2.275(DQ_57) ; also on sheet 126
M_F_DQ_58: DIMMF1.137(DQ_58) DIMMF2.137(DQ_58) ; also on sheet 126
M_F_DQ_59: DIMMF1.282(DQ_59) DIMMF2.282(DQ_59) ; also on sheet 126
M_F_DQ_60: DIMMF1.128(DQ_60) DIMMF2.128(DQ_60) ; also on sheet 126
M_F_DQ_61: DIMMF1.273(DQ_61) DIMMF2.273(DQ_61) ; also on sheet 126
M_F_DQ_62: DIMMF1.135(DQ_62) DIMMF2.135(DQ_62) ; also on sheet 126
M_F_DQ_63: DIMMF1.280(DQ_63) DIMMF2.280(DQ_63) ; also on sheet 126
M_F_DQS_DN_0: DIMMF1.152(DQS0_DN) DIMMF2.152(DQS0_DN) ; also on sheet 126
M_F_DQS_DN_1: DIMMF1.163(DQS1_DN) DIMMF2.163(DQS1_DN) ; also on sheet 126
M_F_DQS_DN_2: DIMMF1.174(DQS2_DN) DIMMF2.174(DQS2_DN) ; also on sheet 126
M_F_DQS_DN_3: DIMMF1.185(DQS3_DN) DIMMF2.185(DQS3_DN) ; also on sheet 126
M_F_DQS_DN_4: DIMMF1.244(DQS4_DN) DIMMF2.244(DQS4_DN) ; also on sheet 126
M_F_DQS_DN_5: DIMMF1.255(DQS5_DN) DIMMF2.255(DQS5_DN) ; also on sheet 126
M_F_DQS_DN_6: DIMMF1.266(DQS6_DN) DIMMF2.266(DQS6_DN) ; also on sheet 126
M_F_DQS_DN_7: DIMMF1.277(DQS7_DN) DIMMF2.277(DQS7_DN) ; also on sheet 126
M_F_DQS_DN_8: DIMMF1.196(DQS8_DN) DIMMF2.196(DQS8_DN) ; also on sheet 126
M_F_DQS_DN_9: DIMMF1.8(DQS9_DN) DIMMF2.8(DQS9_DN) ; also on sheet 126
M_F_DQS_DN_10: DIMMF1.19(DQS10_DN) DIMMF2.19(DQS10_DN) ; also on sheet 126
M_F_DQS_DN_11: DIMMF1.30(DQS11_DN) DIMMF2.30(DQS11_DN) ; also on sheet 126
M_F_DQS_DN_12: DIMMF1.41(DQS12_DN) DIMMF2.41(DQS12_DN) ; also on sheet 126
M_F_DQS_DN_13: DIMMF1.100(DQS13_DN) DIMMF2.100(DQS13_DN) ; also on sheet 126
M_F_DQS_DN_14: DIMMF1.111(DQS14_DN) DIMMF2.111(DQS14_DN) ; also on sheet 126
M_F_DQS_DN_15: DIMMF1.122(DQS15_DN) DIMMF2.122(DQS15_DN) ; also on sheet 126
M_F_DQS_DN_16: DIMMF1.133(DQS16_DN) DIMMF2.133(DQS16_DN) ; also on sheet 126
M_F_DQS_DN_17: DIMMF1.52(DQS17_DN) DIMMF2.52(DQS17_DN) ; also on sheet 126
M_F_DQS_DP_0: DIMMF1.153(DQS0_DP) DIMMF2.153(DQS0_DP) ; also on sheet 126
M_F_DQS_DP_1: DIMMF1.164(DQS1_DP) DIMMF2.164(DQS1_DP) ; also on sheet 126
M_F_DQS_DP_2: DIMMF1.175(DQS2_DP) DIMMF2.175(DQS2_DP) ; also on sheet 126
M_F_DQS_DP_3: DIMMF1.186(DQS3_DP) DIMMF2.186(DQS3_DP) ; also on sheet 126
M_F_DQS_DP_4: DIMMF1.245(DQS4_DP) DIMMF2.245(DQS4_DP) ; also on sheet 126
M_F_DQS_DP_5: DIMMF1.256(DQS5_DP) DIMMF2.256(DQS5_DP) ; also on sheet 126
M_F_DQS_DP_6: DIMMF1.267(DQS6_DP) DIMMF2.267(DQS6_DP) ; also on sheet 126
M_F_DQS_DP_7: DIMMF1.278(DQS7_DP) DIMMF2.278(DQS7_DP) ; also on sheet 126
M_F_DQS_DP_8: DIMMF1.197(DQS8_DP) DIMMF2.197(DQS8_DP) ; also on sheet 126
M_F_DQS_DP_9: DIMMF1.7(DQS9_DP) DIMMF2.7(DQS9_DP) ; also on sheet 126
M_F_DQS_DP_10: DIMMF1.18(DQS10_DP) DIMMF2.18(DQS10_DP) ; also on sheet 126
M_F_DQS_DP_11: DIMMF1.29(DQS11_DP) DIMMF2.29(DQS11_DP) ; also on sheet 126
M_F_DQS_DP_12: DIMMF1.40(DQS12_DP) DIMMF2.40(DQS12_DP) ; also on sheet 126
M_F_DQS_DP_13: DIMMF1.99(DQS13_DP) DIMMF2.99(DQS13_DP) ; also on sheet 126
M_F_DQS_DP_14: DIMMF1.110(DQS14_DP) DIMMF2.110(DQS14_DP) ; also on sheet 126
M_F_DQS_DP_15: DIMMF1.121(DQS15_DP) DIMMF2.121(DQS15_DP) ; also on sheet 126
M_F_DQS_DP_16: DIMMF1.132(DQS16_DP) DIMMF2.132(DQS16_DP) ; also on sheet 126
M_F_DQS_DP_17: DIMMF1.51(DQS17_DP) DIMMF2.51(DQS17_DP) ; also on sheet 126
M_F_ECC_0: DIMMF1.49(CB0) DIMMF2.49(CB0) ; also on sheet 126
M_F_ECC_1: DIMMF1.194(CB1) DIMMF2.194(CB1) ; also on sheet 126
M_F_ECC_2: DIMMF1.56(CB2) DIMMF2.56(CB2) ; also on sheet 126
M_F_ECC_3: DIMMF1.201(CB3) DIMMF2.201(CB3) ; also on sheet 126
M_F_ECC_4: DIMMF1.47(CB4) DIMMF2.47(CB4) ; also on sheet 126
M_F_ECC_5: DIMMF1.192(CB5) DIMMF2.192(CB5) ; also on sheet 126
M_F_ECC_6: DIMMF1.54(CB6) DIMMF2.54(CB6) ; also on sheet 126
M_F_ECC_7: DIMMF1.199(CB7) DIMMF2.199(CB7) ; also on sheet 126
M_F_MA_0: DIMMF1.79(A0) DIMMF2.79(A0) ; also on sheet 126
M_F_MA_1: DIMMF1.72(A1) DIMMF2.72(A1) ; also on sheet 126
M_F_MA_2: DIMMF1.216(A2) DIMMF2.216(A2) ; also on sheet 126
M_F_MA_3: DIMMF1.71(A3) DIMMF2.71(A3) ; also on sheet 126
M_F_MA_4: DIMMF1.214(A4) DIMMF2.214(A4) ; also on sheet 126
M_F_MA_5: DIMMF1.213(A5) DIMMF2.213(A5) ; also on sheet 126
M_F_MA_6: DIMMF1.69(A6) DIMMF2.69(A6) ; also on sheet 126
M_F_MA_7: DIMMF1.211(A7) DIMMF2.211(A7) ; also on sheet 126
M_F_MA_8: DIMMF1.68(A8) DIMMF2.68(A8) ; also on sheet 126
M_F_MA_9: DIMMF1.66(A9) DIMMF2.66(A9) ; also on sheet 126
M_F_MA_10: DIMMF1.225(A10) DIMMF2.225(A10) ; also on sheet 126
M_F_MA_11: DIMMF1.210(A11) DIMMF2.210(A11) ; also on sheet 126
M_F_MA_12: DIMMF1.65(A12) DIMMF2.65(A12) ; also on sheet 126
M_F_MA_13: DIMMF1.232(A13) DIMMF2.232(A13) ; also on sheet 126
M_F_MA_14: DIMMF1.228(A14/WE#) DIMMF2.228(A14/WE#) ; also on sheet 126
M_F_MA_15: DIMMF1.86(A15/CAS#) DIMMF2.86(A15/CAS#) ; also on sheet 126
M_F_MA_16: DIMMF1.82(A16/RAS#) DIMMF2.82(A16/RAS#) ; also on sheet 126
M_F_MA_17: DIMMF1.234(A17) DIMMF2.234(A17) ; also on sheet 126
M_F_ODT_0: DIMMF1.87(ODT0) ; also on sheet 126
M_F_ODT_1: DIMMF1.91(ODT1) ; also on sheet 126
M_F_ODT_2: DIMMF2.87(ODT0) ; also on sheet 126
M_F_ODT_3: DIMMF2.91(ODT1) ; also on sheet 126
M_F_PAR: DIMMF1.222(PAR) DIMMF2.222(PAR) ; also on sheet 126
M_G_ACT_N: DIMMG1.62(ACT#) ; also on sheet 106 125
M_G_ALERT_N: DIMMG1.208(ALERT#) ; also on sheet 106 125
M_G_BA_0: DIMMG1.81(BA0) ; also on sheet 106 125
M_G_BA_1: DIMMG1.224(BA1) ; also on sheet 106 125
M_G_BG_0: DIMMG1.63(BG0) ; also on sheet 106 125
M_G_BG_1: DIMMG1.207(BG1) ; also on sheet 106 125
M_G_C_2: DIMMG1.235(C2) ; also on sheet 106 125
M_G_CKE_0: DIMMG1.60(CKE0) ; also on sheet 125
M_G_CKE_1: DIMMG1.203(CKE1) ; also on sheet 125
M_G_CLK_DN_0: DIMMG1.75(CK0_DN) ; also on sheet 125
M_G_CLK_DN_2: DIMMG1.219(CK1_DN) ; also on sheet 125
M_G_CLK_DP_0: DIMMG1.74(CK0_DP) ; also on sheet 125
M_G_CLK_DP_2: DIMMG1.218(CK1_DP) ; also on sheet 125
M_G_CS_N_0: DIMMG1.84(S0#) ; also on sheet 125
M_G_CS_N_1: DIMMG1.89(S1#) ; also on sheet 125
M_G_CS_N_2: DIMMG1.93(S2_N_C0) ; also on sheet 125
M_G_CS_N_3: DIMMG1.237(S3_N_C1) ; also on sheet 125
M_G_DQ_0: DIMMG1.5(DQ_0) ; also on sheet 106 125
M_G_DQ_1: DIMMG1.150(DQ_1) ; also on sheet 106 125
M_G_DQ_2: DIMMG1.12(DQ_2) ; also on sheet 106 125
M_G_DQ_3: DIMMG1.157(DQ_3) ; also on sheet 106 125
M_G_DQ_4: DIMMG1.3(DQ_4) ; also on sheet 106 125
M_G_DQ_5: DIMMG1.148(DQ_5) ; also on sheet 106 125
M_G_DQ_6: DIMMG1.10(DQ_6) ; also on sheet 106 125
M_G_DQ_7: DIMMG1.155(DQ_7) ; also on sheet 106 125
M_G_DQ_8: DIMMG1.16(DQ_8) ; also on sheet 106 125
M_G_DQ_9: DIMMG1.161(DQ_9) ; also on sheet 106 125
M_G_DQ_10: DIMMG1.23(DQ_10) ; also on sheet 106 125
M_G_DQ_11: DIMMG1.168(DQ_11) ; also on sheet 106 125
M_G_DQ_12: DIMMG1.14(DQ_12) ; also on sheet 106 125
M_G_DQ_13: DIMMG1.159(DQ_13) ; also on sheet 106 125
M_G_DQ_14: DIMMG1.21(DQ_14) ; also on sheet 106 125
M_G_DQ_15: DIMMG1.166(DQ_15) ; also on sheet 106 125
M_G_DQ_16: DIMMG1.27(DQ_16) ; also on sheet 106 125
M_G_DQ_17: DIMMG1.172(DQ_17) ; also on sheet 106 125
M_G_DQ_18: DIMMG1.34(DQ_18) ; also on sheet 106 125
M_G_DQ_19: DIMMG1.179(DQ_19) ; also on sheet 106 125
M_G_DQ_20: DIMMG1.25(DQ_20) ; also on sheet 106 125
M_G_DQ_21: DIMMG1.170(DQ_21) ; also on sheet 106 125
M_G_DQ_22: DIMMG1.32(DQ_22) ; also on sheet 106 125
M_G_DQ_23: DIMMG1.177(DQ_23) ; also on sheet 106 125
M_G_DQ_24: DIMMG1.38(DQ_24) ; also on sheet 106 125
M_G_DQ_25: DIMMG1.183(DQ_25) ; also on sheet 106 125
M_G_DQ_26: DIMMG1.45(DQ_26) ; also on sheet 106 125
M_G_DQ_27: DIMMG1.190(DQ_27) ; also on sheet 106 125
M_G_DQ_28: DIMMG1.36(DQ_28) ; also on sheet 106 125
M_G_DQ_29: DIMMG1.181(DQ_29) ; also on sheet 106 125
M_G_DQ_30: DIMMG1.43(DQ_30) ; also on sheet 106 125
M_G_DQ_31: DIMMG1.188(DQ_31) ; also on sheet 106 125
M_G_DQ_32: DIMMG1.97(DQ_32) ; also on sheet 106 125
M_G_DQ_33: DIMMG1.242(DQ_33) ; also on sheet 106 125
M_G_DQ_34: DIMMG1.104(DQ_34) ; also on sheet 106 125
M_G_DQ_35: DIMMG1.249(DQ_35) ; also on sheet 106 125
M_G_DQ_36: DIMMG1.95(DQ_36) ; also on sheet 106 125
M_G_DQ_37: DIMMG1.240(DQ_37) ; also on sheet 106 125
M_G_DQ_38: DIMMG1.102(DQ_38) ; also on sheet 106 125
M_G_DQ_39: DIMMG1.247(DQ_39) ; also on sheet 106 125
M_G_DQ_40: DIMMG1.108(DQ_40) ; also on sheet 106 125
M_G_DQ_41: DIMMG1.253(DQ_41) ; also on sheet 106 125
M_G_DQ_42: DIMMG1.115(DQ_42) ; also on sheet 106 125
M_G_DQ_43: DIMMG1.260(DQ_43) ; also on sheet 106 125
M_G_DQ_44: DIMMG1.106(DQ_44) ; also on sheet 106 125
M_G_DQ_45: DIMMG1.251(DQ_45) ; also on sheet 106 125
M_G_DQ_46: DIMMG1.113(DQ_46) ; also on sheet 106 125
M_G_DQ_47: DIMMG1.258(DQ_47) ; also on sheet 106 125
M_G_DQ_48: DIMMG1.119(DQ_48) ; also on sheet 106 125
M_G_DQ_49: DIMMG1.264(DQ_49) ; also on sheet 106 125
M_G_DQ_50: DIMMG1.126(DQ_50) ; also on sheet 106 125
M_G_DQ_51: DIMMG1.271(DQ_51) ; also on sheet 106 125
M_G_DQ_52: DIMMG1.117(DQ_52) ; also on sheet 106 125
M_G_DQ_53: DIMMG1.262(DQ_53) ; also on sheet 106 125
M_G_DQ_54: DIMMG1.124(DQ_54) ; also on sheet 106 125
M_G_DQ_55: DIMMG1.269(DQ_55) ; also on sheet 106 125
M_G_DQ_56: DIMMG1.130(DQ_56) ; also on sheet 106 125
M_G_DQ_57: DIMMG1.275(DQ_57) ; also on sheet 106 125
M_G_DQ_58: DIMMG1.137(DQ_58) ; also on sheet 106 125
M_G_DQ_59: DIMMG1.282(DQ_59) ; also on sheet 106 125
M_G_DQ_60: DIMMG1.128(DQ_60) ; also on sheet 106 125
M_G_DQ_61: DIMMG1.273(DQ_61) ; also on sheet 106 125
M_G_DQ_62: DIMMG1.135(DQ_62) ; also on sheet 106 125
M_G_DQ_63: DIMMG1.280(DQ_63) ; also on sheet 106 125
M_G_DQS_DN_0: DIMMG1.152(DQS0_DN) ; also on sheet 106 125
M_G_DQS_DN_1: DIMMG1.163(DQS1_DN) ; also on sheet 106 125
M_G_DQS_DN_2: DIMMG1.174(DQS2_DN) ; also on sheet 106 125
M_G_DQS_DN_3: DIMMG1.185(DQS3_DN) ; also on sheet 106 125
M_G_DQS_DN_4: DIMMG1.244(DQS4_DN) ; also on sheet 106 125
M_G_DQS_DN_5: DIMMG1.255(DQS5_DN) ; also on sheet 106 125
M_G_DQS_DN_6: DIMMG1.266(DQS6_DN) ; also on sheet 106 125
M_G_DQS_DN_7: DIMMG1.277(DQS7_DN) ; also on sheet 106 125
M_G_DQS_DN_8: DIMMG1.196(DQS8_DN) ; also on sheet 106 125
M_G_DQS_DN_9: DIMMG1.8(DQS9_DN) ; also on sheet 106 125
M_G_DQS_DN_10: DIMMG1.19(DQS10_DN) ; also on sheet 106 125
M_G_DQS_DN_11: DIMMG1.30(DQS11_DN) ; also on sheet 106 125
M_G_DQS_DN_12: DIMMG1.41(DQS12_DN) ; also on sheet 106 125
M_G_DQS_DN_13: DIMMG1.100(DQS13_DN) ; also on sheet 106 125
M_G_DQS_DN_14: DIMMG1.111(DQS14_DN) ; also on sheet 106 125
M_G_DQS_DN_15: DIMMG1.122(DQS15_DN) ; also on sheet 106 125
M_G_DQS_DN_16: DIMMG1.133(DQS16_DN) ; also on sheet 106 125
M_G_DQS_DN_17: DIMMG1.52(DQS17_DN) ; also on sheet 106 125
M_G_DQS_DP_0: DIMMG1.153(DQS0_DP) ; also on sheet 106 125
M_G_DQS_DP_1: DIMMG1.164(DQS1_DP) ; also on sheet 106 125
M_G_DQS_DP_2: DIMMG1.175(DQS2_DP) ; also on sheet 106 125
M_G_DQS_DP_3: DIMMG1.186(DQS3_DP) ; also on sheet 106 125
M_G_DQS_DP_4: DIMMG1.245(DQS4_DP) ; also on sheet 106 125
M_G_DQS_DP_5: DIMMG1.256(DQS5_DP) ; also on sheet 106 125
M_G_DQS_DP_6: DIMMG1.267(DQS6_DP) ; also on sheet 106 125
M_G_DQS_DP_7: DIMMG1.278(DQS7_DP) ; also on sheet 106 125
M_G_DQS_DP_8: DIMMG1.197(DQS8_DP) ; also on sheet 106 125
M_G_DQS_DP_9: DIMMG1.7(DQS9_DP) ; also on sheet 106 125
M_G_DQS_DP_10: DIMMG1.18(DQS10_DP) ; also on sheet 106 125
M_G_DQS_DP_11: DIMMG1.29(DQS11_DP) ; also on sheet 106 125
M_G_DQS_DP_12: DIMMG1.40(DQS12_DP) ; also on sheet 106 125
M_G_DQS_DP_13: DIMMG1.99(DQS13_DP) ; also on sheet 106 125
M_G_DQS_DP_14: DIMMG1.110(DQS14_DP) ; also on sheet 106 125
M_G_DQS_DP_15: DIMMG1.121(DQS15_DP) ; also on sheet 106 125
M_G_DQS_DP_16: DIMMG1.132(DQS16_DP) ; also on sheet 106 125
M_G_DQS_DP_17: DIMMG1.51(DQS17_DP) ; also on sheet 106 125
M_G_ECC_0: DIMMG1.49(CB0) ; also on sheet 106 125
M_G_ECC_1: DIMMG1.194(CB1) ; also on sheet 106 125
M_G_ECC_2: DIMMG1.56(CB2) ; also on sheet 106 125
M_G_ECC_3: DIMMG1.201(CB3) ; also on sheet 106 125
M_G_ECC_4: DIMMG1.47(CB4) ; also on sheet 106 125
M_G_ECC_5: DIMMG1.192(CB5) ; also on sheet 106 125
M_G_ECC_6: DIMMG1.54(CB6) ; also on sheet 106 125
M_G_ECC_7: DIMMG1.199(CB7) ; also on sheet 106 125
M_G_MA_0: DIMMG1.79(A0) ; also on sheet 106 125
M_G_MA_1: DIMMG1.72(A1) ; also on sheet 106 125
M_G_MA_2: DIMMG1.216(A2) ; also on sheet 106 125
M_G_MA_3: DIMMG1.71(A3) ; also on sheet 106 125
M_G_MA_4: DIMMG1.214(A4) ; also on sheet 106 125
M_G_MA_5: DIMMG1.213(A5) ; also on sheet 106 125
M_G_MA_6: DIMMG1.69(A6) ; also on sheet 106 125
M_G_MA_7: DIMMG1.211(A7) ; also on sheet 106 125
M_G_MA_8: DIMMG1.68(A8) ; also on sheet 106 125
M_G_MA_9: DIMMG1.66(A9) ; also on sheet 106 125
M_G_MA_10: DIMMG1.225(A10) ; also on sheet 106 125
M_G_MA_11: DIMMG1.210(A11) ; also on sheet 106 125
M_G_MA_12: DIMMG1.65(A12) ; also on sheet 106 125
M_G_MA_13: DIMMG1.232(A13) ; also on sheet 106 125
M_G_MA_14: DIMMG1.228(A14/WE#) ; also on sheet 106 125
M_G_MA_15: DIMMG1.86(A15/CAS#) ; also on sheet 106 125
M_G_MA_16: DIMMG1.82(A16/RAS#) ; also on sheet 106 125
M_G_MA_17: DIMMG1.234(A17) ; also on sheet 106 125
M_G_ODT_0: DIMMG1.87(ODT0) ; also on sheet 125
M_G_ODT_1: DIMMG1.91(ODT1) ; also on sheet 125
M_G_PAR: DIMMG1.222(PAR) ; also on sheet 106 125
M_GH_RESET_N: DIMMG1.58(RESET#) ; also on sheet 104 105 106 129
M_GH_VREF: C881.1 DIMMG1.146(VREFCA) ; also on sheet 104 105 106 129
NV_SAVE_CHF_DIMM0: DIMMF1.230(RFU_2) ; also on sheet 52
NV_SAVE_CHF_DIMM1: DIMMF2.230(RFU_2) ; also on sheet 52
NV_SAVE_CHG_DIMM0: DIMMG1.230(RFU_2) ; also on sheet 52
PVPP_EF: DIMMF1.142(VPP_0) DIMMF1.143(VPP_1) DIMMF1.238(SA2) DIMMF1.284(VDDSPD) DIMMF1.286(VPP_2) DIMMF1.287(VPP_3) DIMMF1.288(VPP_4) DIMMF2.139(SA0) DIMMF2.142(VPP_0) DIMMF2.143(VPP_1) DIMMF2.238(SA2) DIMMF2.284(VDDSPD) DIMMF2.286(VPP_2) DIMMF2.287(VPP_3) DIMMF2.288(VPP_4) ; also on sheet 17 110 111 160
PVPP_GH: DIMMG1.142(VPP_0) DIMMG1.143(VPP_1) DIMMG1.284(VDDSPD) DIMMG1.286(VPP_2) DIMMG1.287(VPP_3) DIMMG1.288(VPP_4) ; also on sheet 12 104 105 106 160
PVTT_EF: DIMMF1.77(VTT_0) DIMMF1.221(VTT_1) DIMMF2.77(VTT_0) DIMMF2.221(VTT_1) ; also on sheet 19 110 111
PVTT_GH: DIMMG1.77(VTT_0) DIMMG1.221(VTT_1) ; also on sheet 14 104 105 106
SMB_DDR_EF_SCL_LVC2V5: DIMMF1.141(SCL) DIMMF2.141(SCL) ; also on sheet 110 111 160
SMB_DDR_EF_SDA_LVC2V5: DIMMF1.285(SDA) DIMMF2.285(SDA) ; also on sheet 110 111 160
SMB_DDR_GH_SCL_LVC2V5: DIMMG1.141(SCL) ; also on sheet 104 105 106 160
SMB_DDR_GH_SDA_LVC2V5: DIMMG1.285(SDA) ; also on sheet 104 105 106 160

Not connected (* = marked no-connect by the designer): DIMMF1 144(RFU_3)* 205(RFU_0)* 227(RFU_1)* NP1* NP2* NP3*; DIMMF2 144(RFU_3)* 205(RFU_0)* 227(RFU_1)* NP1* NP2* NP3*; DIMMG1 144(RFU_3)* 205(RFU_0)* 227(RFU_1)* NP1* NP2* NP3*

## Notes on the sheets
sheet 107
- DDR4 DIMM CPU1 CHG-1
- FAB1 REV021 20150424
- FAB1 REV003 20150318
- DIMMG1
- I2C Address = A0
- Chip Select Signal DIMM Mapping
- ODT Signal DIMM Mapping
- CKE Signal DIMM Mapping
- DDR4 Clock Signal DIMM Pin Mapping (UDIMM/RDIMM support)
- DIMM
- DIMM Pin
- CPU Signal
- DIMM
- DIMM Pin
- CPU Signal
- DIMM
- DIMM Pin
- CPU Signal
- DIMM
- DIMM Pin
- CPU Signal
- DIMM0
- 83
- CS_N0
- DIMM0
- 86
- ODT0
- DIMM0
- 59
- CKE0
- DIMM0
- 73
- CLK_DP0
- DIMM0
- 88
- CS_N1
- DIMM0
- 90
- ODT1
- DIMM0
- 200
- CKE1
- DIMM0
- 74
- CLK_DN0
- DIMM0
- 92
- CS_N2/C[0]
- DIMM1
- 86
- ODT2
- DIMM1
- 59
- CKE2
- DIMM0
- 215
- CLK_DP2
- DIMM0
- 234
- CS_N3/C[1]
- DIMM1
- 90
- ODT3
- DIMM1
- 200
- CKE3
- DIMM0
- 216
- CLK_DN2
- DIMM1
- 83
- CS_N4
- DIMM1
- 73
- CLK_DP1
- DIMM1
- 88
- CS_N5
- DIMM1
- 74
- CLK_DN1
- DIMM1
- 92
- CS_N6/C[3]
- DIMM1
- 215
- CLK_DP3
- DIMM1
- 234
- CS_N7/C[4]
- DIMM1
- 216
- CLK_DN3
sheet 108
- DDR4 DIMM CPU1 CHF-2
- FAB1 REV021 20150424
- FAB1 REV003 20150318
- DIMMF2
- I2C Address = AA
- Chip Select Signal DIMM Mapping
- ODT Signal DIMM Mapping
- CKE Signal DIMM Mapping
- DDR4 Clock Signal DIMM Pin Mapping (UDIMM/RDIMM support)
- DIMM
- DIMM Pin
- CPU Signal
- DIMM
- DIMM Pin
- CPU Signal
- DIMM
- DIMM Pin
- CPU Signal
- DIMM
- DIMM Pin
- CPU Signal
- DIMM0
- 83
- CS_N0
- DIMM0
- 86
- ODT0
- DIMM0
- 59
- CKE0
- DIMM0
- 73
- CLK_DP0
- DIMM0
- 88
- CS_N1
- DIMM0
- 90
- ODT1
- DIMM0
- 200
- CKE1
- DIMM0
- 74
- CLK_DN0
- DIMM0
- 92
- CS_N2/C[0]
- DIMM1
- 86
- ODT2
- DIMM1
- 59
- CKE2
- DIMM0
- 215
- CLK_DP2
- DIMM0
- 234
- CS_N3/C[1]
- DIMM1
- 90
- ODT3
- DIMM1
- 200
- CKE3
- DIMM0
- 216
- CLK_DN2
- DIMM1
- 83
- CS_N4
- DIMM1
- 73
- CLK_DP1
- DIMM1
- 88
- CS_N5
- DIMM1
- 74
- CLK_DN1
- DIMM1
- 92
- CS_N6/C[3]
- DIMM1
- 215
- CLK_DP3
- DIMM1
- 234
- CS_N7/C[4]
- DIMM1
- 216
- CLK_DN3
sheet 109
- DDR4 DIMM CPU1 CHF-1
- FAB1 REV021 20150424
- FAB1 REV003 20150318
- DIMMF1
- I2C Address = A8
- Chip Select Signal DIMM Mapping
- ODT Signal DIMM Mapping
- CKE Signal DIMM Mapping
- DDR4 Clock Signal DIMM Pin Mapping (UDIMM/RDIMM support)
- DIMM
- DIMM Pin
- CPU Signal
- DIMM
- DIMM Pin
- CPU Signal
- DIMM
- DIMM Pin
- CPU Signal
- DIMM
- DIMM Pin
- CPU Signal
- DIMM0
- 83
- CS_N0
- DIMM0
- 86
- ODT0
- DIMM0
- 59
- CKE0
- DIMM0
- 73
- CLK_DP0
- DIMM0
- 88
- CS_N1
- DIMM0
- 90
- ODT1
- DIMM0
- 200
- CKE1
- DIMM0
- 74
- CLK_DN0
- DIMM0
- 92
- CS_N2/C[0]
- DIMM1
- 86
- ODT2
- DIMM1
- 59
- CKE2
- DIMM0
- 215
- CLK_DP2
- DIMM0
- 234
- CS_N3/C[1]
- DIMM1
- 90
- ODT3
- DIMM1
- 200
- CKE3
- DIMM0
- 216
- CLK_DN2
- DIMM1
- 83
- CS_N4
- DIMM1
- 73
- CLK_DP1
- DIMM1
- 88
- CS_N5
- DIMM1
- 74
- CLK_DN1
- DIMM1
- 92
- CS_N6/C[3]
- DIMM1
- 215
- CLK_DP3
- DIMM1
- 234
- CS_N7/C[4]
- DIMM1
- 216
- CLK_DN3
